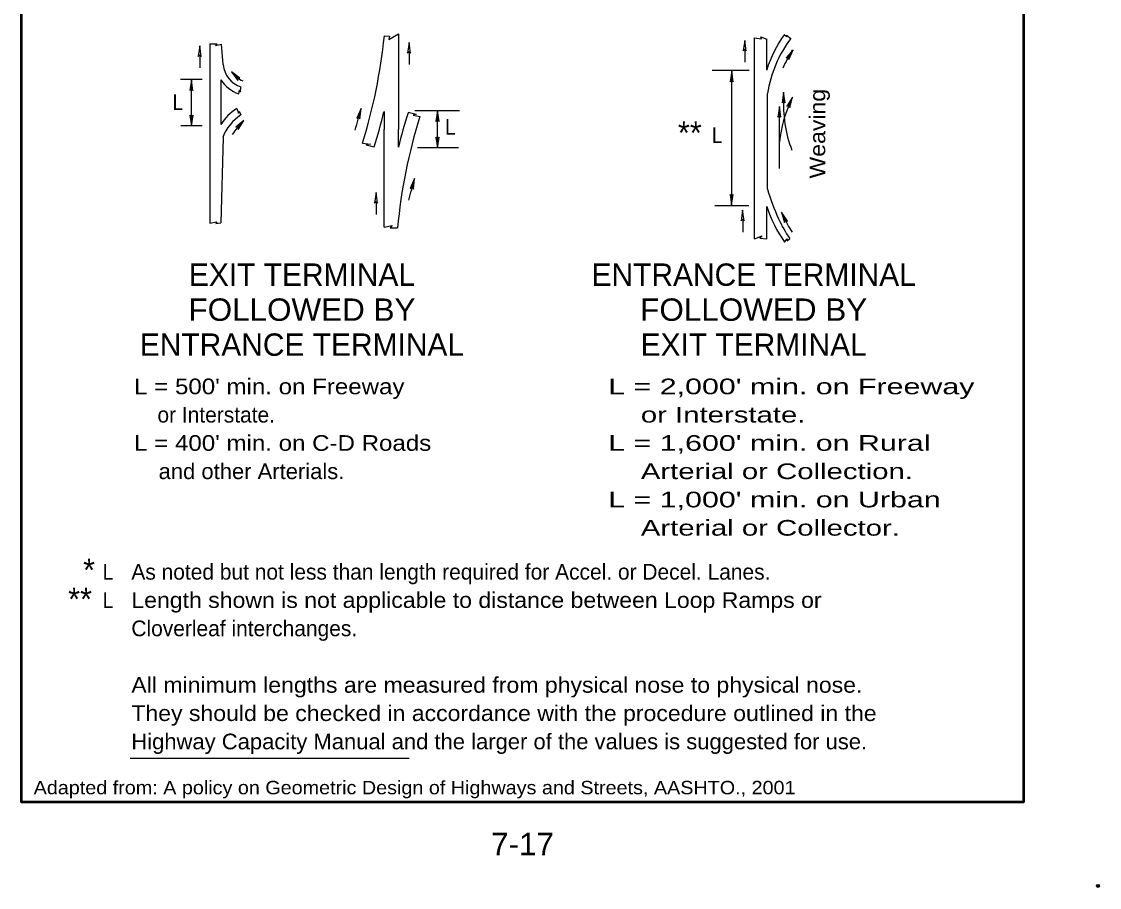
# Model space of a CAD drawing. Extents: x -5.247 to -4.572, y 0.948 to 1.832.
# Drawn here: x -5.199 to -4.572, y 0.948 to 1.452 of the extents above; entities that cross this region are included whole.
import ezdxf
from ezdxf.enums import TextEntityAlignment as Align

# ---------------------------------------------------------------- set-up
doc = ezdxf.new("R2010")
doc.units = 0
doc.header["$LTSCALE"] = 0.0036
doc.header["$PDMODE"] = 32
doc.header["$PDSIZE"] = 0.0018
doc.linetypes.add('MEDIUM_DASHED', pattern=[4.5, 3, -1.5])
doc.layers.add('1', color=7, linetype='Continuous', lineweight=25)

msp = doc.modelspace()

# ---------------------------------------------------------------- linework, layer by layer
at = {"layer": '1'}
for p, q in [((-4.979858, 1.445033), (-4.979858, 1.389508)), ((-5.0896, 1.439258), (-5.0896, 1.334908)), ((-5.081858, 1.427183), (-5.082808, 1.439075)), ((-4.772533, 1.325792), (-4.772533, 1.442767)), ((-4.765483, 1.423958), (-4.765483, 1.441992)), ((-5.095483, 1.432592), (-5.095483, 1.425333)), ((-4.973608, 1.43455), (-4.973608, 1.427292)), ((-4.778225, 1.435808), (-4.778225, 1.42855)), ((-5.0941, 1.418467), (-5.106842, 1.418467)), ((-5.083258, 1.418425), (-5.083258, 1.392383)), ((-4.775708, 1.423842), (-4.797192, 1.423842)), ((-4.765083, 1.354758), (-4.765083, 1.410375)), ((-4.98815, 1.3998), (-4.98815, 1.389433)), ((-4.970392, 1.400533), (-4.944408, 1.400533)), ((-4.758058, 1.366758), (-4.758058, 1.4001)), ((-5.0941, 1.391617), (-5.106567, 1.391617)), ((-4.98815, 1.332517), (-4.98815, 1.389433)), ((-4.979858, 1.379142), (-4.979858, 1.389508)), ((-5.08185, 1.384758), (-5.083258, 1.335092)), ((-4.968817, 1.378975), (-4.944908, 1.378975)), ((-4.992808, 1.347133), (-4.992808, 1.339875)), ((-4.775908, 1.345017), (-4.795725, 1.345017)), ((-4.765483, 1.325792), (-4.765483, 1.3445)), ((-4.7794, 1.336842), (-4.7794, 1.329583)), ((-4.984783, 1.332125), (-4.98045, 1.332083)), ((-5.13605, 1.023358), (-4.973692, 1.023358))]:
    msp.add_line(p, q, dxfattribs=at)
at = {"layer": '1', "linetype": 'MEDIUM_DASHED'}
for p, q in [((-5.100342, 1.391617), (-5.100342, 1.418225)), ((-4.785817, 1.345017), (-4.785817, 1.423467)), ((-4.957158, 1.378975), (-4.957158, 1.400375))]:
    msp.add_line(p, q, dxfattribs=at)
at = {"layer": '1', "lineweight": 53}
msp.add_lwpolyline([(-5.1993, 1.789417), (-4.615967, 1.789417), (-4.615967, 0.99775), (-5.1993, 0.99775)], close=True, dxfattribs=at)
at = {"layer": '1'}
for points in [[(-4.988067, 1.443867), (-4.985183, 1.44385), (-4.985575, 1.441892), (-4.979858, 1.445033)], [(-4.772533, 1.442767), (-4.768608, 1.442258), (-4.768825, 1.443383), (-4.765483, 1.441992)], [(-4.755233, 1.444825), (-4.753975, 1.443383), (-4.753975, 1.444292), (-4.751458, 1.442492)], [(-5.0896, 1.439258), (-5.085425, 1.43925), (-5.0864, 1.438267), (-5.082808, 1.439075)], [(-5.072883, 1.410242), (-5.072483, 1.412308), (-5.071925, 1.4113), (-5.0716, 1.414183)], [(-5.074058, 1.401625), (-5.072942, 1.398917), (-5.0726, 1.400042), (-5.07165, 1.397908)], [(-4.97415, 1.399592), (-4.969533, 1.39835), (-4.971225, 1.397792), (-4.967408, 1.39705)], [(-5.00085, 1.381492), (-4.996067, 1.380908), (-4.99865, 1.380558), (-4.993942, 1.379342)], [(-5.0896, 1.334908), (-5.085567, 1.335558), (-5.086158, 1.334583), (-5.083258, 1.335092)], [(-4.98815, 1.332517), (-4.983558, 1.3335), (-4.984783, 1.332125)], [(-4.772533, 1.325792), (-4.768158, 1.327425), (-4.7695, 1.326075), (-4.765483, 1.325792)], [(-4.755142, 1.323842), (-4.753525, 1.325842), (-4.753525, 1.3245), (-4.752075, 1.326033)]]:
    msp.add_lwpolyline(points, dxfattribs=at)
for points in [[(-5.096508, 1.43195), (-5.095575, 1.433075), (-5.094658, 1.43195), (-5.095575, 1.438117)], [(-4.974633, 1.433908), (-4.9737, 1.435033), (-4.972783, 1.433908), (-4.9737, 1.440075)], [(-4.779242, 1.435167), (-4.778317, 1.436292), (-4.7774, 1.435167), (-4.778317, 1.441333)], [(-4.75425, 1.431175), (-4.752875, 1.431625), (-4.7527, 1.430183), (-4.750167, 1.435883)], [(-5.101342, 1.412058), (-5.100408, 1.413183), (-5.099492, 1.412058), (-5.100408, 1.418225)], [(-5.073475, 1.417958), (-5.073567, 1.419408), (-5.072133, 1.419217), (-5.077017, 1.423083)], [(-4.786808, 1.417133), (-4.785875, 1.418258), (-4.784958, 1.417133), (-4.785875, 1.4233)], [(-4.756558, 1.405008), (-4.755642, 1.406142), (-4.754708, 1.405033), (-4.755692, 1.411183)], [(-4.753733, 1.402967), (-4.752433, 1.403625), (-4.752042, 1.402225), (-4.750433, 1.408258)], [(-5.004133, 1.396017), (-5.002942, 1.39685), (-5.00235, 1.395533), (-5.001608, 1.401717)], [(-4.958092, 1.394133), (-4.957158, 1.395258), (-4.956242, 1.394133), (-4.957158, 1.4003)], [(-4.759017, 1.3966), (-4.758083, 1.397725), (-4.757167, 1.3966), (-4.758083, 1.402767)], [(-5.099442, 1.397717), (-5.100358, 1.396592), (-5.101283, 1.397717), (-5.100358, 1.391542)], [(-5.074617, 1.390675), (-5.073183, 1.390917), (-5.073233, 1.389467), (-5.069867, 1.394717)], [(-4.9562, 1.384975), (-4.957117, 1.38385), (-4.95805, 1.384975), (-4.957117, 1.3788)], [(-4.972975, 1.355142), (-4.971783, 1.355975), (-4.971192, 1.354658), (-4.97045, 1.360842)], [(-4.993825, 1.346492), (-4.9929, 1.347617), (-4.991983, 1.346492), (-4.9929, 1.352658)], [(-4.785, 1.351642), (-4.785917, 1.350517), (-4.78685, 1.351642), (-4.785917, 1.345467)], [(-4.780417, 1.3362), (-4.779492, 1.337325), (-4.778575, 1.3362), (-4.779492, 1.342367)], [(-4.75515, 1.33535), (-4.754775, 1.336767), (-4.753475, 1.336125), (-4.756892, 1.341342)]]:
    msp.add_lwpolyline(points, close=True, dxfattribs=at)
for centre, radius, start, end in [((-5.306754, 1.476662), 0.320372, 342.71809, 354.1245), ((-4.692981, 1.401019), 0.076109, 144.86867, 162.2867), ((-4.692621, 1.398578), 0.073418, 143.26949, 170.75231), ((-4.692621, 1.398578), 0.068737, 147.48465, 157.35082), ((-5.066988, 1.42837), 0.014914, 184.54623, 252.00119), ((-5.066988, 1.42837), 0.019065, 211.44088, 252.00119), ((-5.064943, 1.431424), 0.014744, 214.75549, 248.27566), ((-4.684968, 1.374807), 0.073418, 154.24103, 174.25014), ((-4.683542, 1.403359), 0.072143, 175.76489, 201.11689), ((-5.057385, 1.375828), 0.030713, 122.87568, 147.38329), ((-5.306754, 1.476662), 0.314142, 343.81468, 346.1989), ((-5.306754, 1.476662), 0.327597, 342.71809, 346.42588), ((-5.057385, 1.375828), 0.026286, 122.87568, 159.94663), ((-5.007417, 1.333087), 0.087556, 135.57503, 142.38249), ((-4.661505, 1.301875), 0.320372, 162.71809, 174.58949), ((-4.661505, 1.301875), 0.327597, 162.71809, 166.35741), ((-5.275598, 1.435787), 0.314142, 343.81468, 346.1989), ((-4.640527, 1.391285), 0.129803, 196.34358, 204.55041), ((-4.692888, 1.367644), 0.076109, 197.7133, 215.13133), ((-4.693075, 1.36754), 0.072143, 204.73354, 215.13133), ((-4.693085, 1.36754), 0.068964, 204.73354, 213.34945)]:
    msp.add_arc(centre, radius, start, end, dxfattribs=at)
msp.add_point((-4.572675, 0.948942), dxfattribs=at)

# ---------------------------------------------------------------- texts
at = {"layer": '1', "width": 1.1}
msp.add_text('Weaving', height=0.009117, rotation=90, dxfattribs=at).set_placement((-4.731417, 1.360883))
at = {"layer": '1'}
for s, height, width, p in [('L', 0.009117, 0.9, (-5.111383, 1.400825)), ('L', 0.009117, 0.9, (-4.952667, 1.386425)), ('L', 0.009117, 0.9, (-4.797375, 1.381517)), ("L = 500' min. on Freeway", 0.009117, 1.15, (-5.133742, 1.235233)), ("L = 2,000' min. on Freeway", 0.009117, 1.45, (-4.857733, 1.235233)), ('    or Interstate.', 0.009117, 1.4, (-4.857733, 1.218767)), ("L = 400' min. on C-D Roads", 0.009117, 1.15, (-5.133742, 1.2023)), ("L = 1,600' min. on Rural", 0.009117, 1.45, (-4.857733, 1.2023)), ('    and other Arterials.', 0.009117, 1.05, (-5.133742, 1.185833)), ('    Arterial or Collection.', 0.009117, 1.4, (-4.857733, 1.185833)), ("L = 1,000' min. on Urban", 0.009117, 1.45, (-4.857733, 1.169367)), ('    Arterial or Collector.', 0.009117, 1.4, (-4.857733, 1.1529)), ('L', 0.009117, 0.9, (-5.152025, 1.127292)), ('L', 0.009117, 0.9, (-5.152025, 1.110825)), ('Length shown is not applicable to distance between Loop Ramps or', 0.009117, 1.1, (-5.135383, 1.110825)), ('All minimum lengths are measured from physical nose to physical nose.', 0.009117, 1.1, (-5.135383, 1.061425)), ('They should be checked in accordance with the procedure outlined in the', 0.009117, 1.1, (-5.135383, 1.044958)), ('Highway Capacity Manual and the larger of the values is suggested for use.', 0.009117, 1.05, (-5.135383, 1.028492)), ('Adapted from: A policy on Geometric Design of Highways and Streets, AASHTO., 2001', 0.007817, 1.1, (-5.19225, 1.002292))]:
    msp.add_text(s, height=height, dxfattribs=dict(at, width=width)).set_placement(p)
for s, height, p in [('**', 0.01335, (-4.817208, 1.380808)), ('    or Interstate.', 0.009117, (-5.133742, 1.218767)), ('*', 0.01335, (-5.163475, 1.126242)), ('As noted but not less than length required for Accel. or Decel. Lanes.', 0.009117, (-5.135383, 1.127292)), ('**', 0.01335, (-5.172183, 1.109275)), ('Cloverleaf interchanges.', 0.009117, (-5.135383, 1.094358))]:
    msp.add_text(s, height=height, dxfattribs=at).set_placement(p)
for s, p in [('ENTRANCE TERMINAL', (-4.773058, 1.298375)), ('EXIT TERMINAL', (-5.036058, 1.298375)), ('ENTRANCE TERMINAL', (-5.036058, 1.257625)), ('EXIT TERMINAL', (-4.773058, 1.257625))]:
    msp.add_text(s, height=0.01303, dxfattribs=at).set_placement(p, align=Align.CENTER)
at = {"layer": '1', "width": 1.05}
for s, p in [('FOLLOWED BY', (-5.036054, 1.278)), ('FOLLOWED BY', (-4.773054, 1.278)), ('7-17', (-4.907637, 0.966833))]:
    msp.add_text(s, height=0.01303, dxfattribs=at).set_placement(p, align=Align.CENTER)

doc.saveas('drawing.dxf')
